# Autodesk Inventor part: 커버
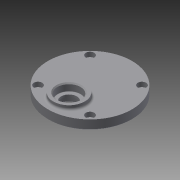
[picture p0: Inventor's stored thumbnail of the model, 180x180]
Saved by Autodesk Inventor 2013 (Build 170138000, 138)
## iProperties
Created: 2015-07
Part Number: 커버
Material: 일반
Document SubType Name: Modeling
Designer: user
Density: 1 g/cm^3
Author: user
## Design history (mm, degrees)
sketch "스케치1"
  geometry: C1 r 40 at (0, 0); 1 further point
  constraints: 1 centre point, 1 coincident
  dimensions: "d0" = 80 diameter of C1
extrude "돌출1" new body sketch "스케치1" distance "d1" = 9; taper "d2" = 0 deg
sketch "스케치2"
  geometry: L1 (0, 0)-(0, 11); L2 (0, 0)-(0, -20); C1 r 40 at (0, 0) reference; C2 r 14 at (0, 11); C3 r 14 at (0, -20)
  constraints: 4 end point, 2 centre point, 2 coincident, 1 collinear, 1 vertical
  dimensions: "d3" = 11 distance of L1.start L1.end; "d4" = 20 distance of L1.start L2.end; "d5" = 28 diameter of C2; "d6" = 28 diameter of C3
extrude "돌출2" join sketch "스케치2" distance "d7" = 3; taper "d8" = 0 deg
sketch "스케치3"
  geometry: L1 (0, 0)-(0, -20); C1 r 40 at (0, 0) reference; C2 r 15 at (0, -20)
  constraints: 2 end point, 1 centre point, 1 coincident, 1 vertical
  dimensions: "d9" = 20 distance of L1.start L1.end; "d11" = 30 diameter of C2
extrude "돌출3" join sketch "스케치3" distance "d12" = 4; taper "d13" = 0 deg
fillet "모깎기1" dims "d14" = 2
chamfer "모따기1" distance "d15" = 1; stored, may be unused: second distance "d16" = 2, angle "d17" = 45 deg
hole "구멍1" diameter "d20" = 15; stored, may be unused: countersink angle "d24" = 90 deg, drill point angle "d26" = 0 deg; dims "d18" = 10, "d19" = 10, "d21" = 6, "d22" = 22, "d23" = 7, "d25" = 10
hole "구멍2" diameter "d29" = 22; stored, may be unused: countersink angle "d33" = 90 deg, drill point angle "d35" = 0 deg; dims "d27" = 10, "d28" = 10, "d30" = 6, "d31" = 22, "d32" = 7, "d34" = 7
hole "구멍3" diameter "d38" = 18; stored, may be unused: countersink angle "d42" = 90 deg, drill point angle "d44" = 0 deg; dims "d36" = 10, "d37" = 10, "d39" = 6, "d40" = 22, "d41" = 7, "d43" = 8
chamfer "모따기2" distance "d45" = 1; stored, may be unused: second distance "d46" = 2, angle "d47" = 45 deg
fillet "모깎기2" dims "d48" = 0.3
fillet "모깎기3" dims "d49" = 2
sketch "스케치4" dims "d50" = 70
  geometry: L1 (0, 0)-(24.749, 24.749); L2 (0, 0)-(35, 0); C1 r 40 at (0, 0) reference
  constraints: 4 end point, 1 coincident, 1 equal length, 1 horizontal, 3 other
  dimensions: "d51" = 45 deg angle of L2 L1
hole "구멍4" sketch "스케치4" at (24.749, 24.749) diameter "d52" = 4.5; stored, may be unused: countersink angle "d56" = 90 deg, drill point angle "d58" = 0 deg; dims "d53" = 6, "d54" = 8, "d55" = 4.4, "d57" = 10
node "솔리드1"
pattern_circular "원형 패턴1" dims angle "d60" = 360 deg
